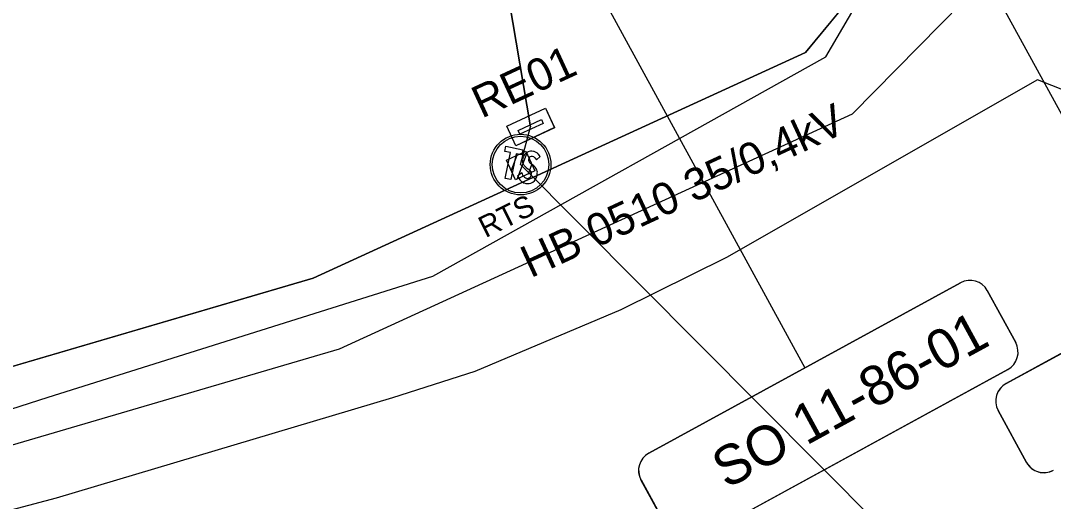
# Model space of a CAD drawing. Extents: x -9100 to -8660, y -10901 to -10569.
# Drawn here: x -8996.47 to -8948.33, y -10841.15 to -10818.76 of the extents above; entities that cross this region are included whole.
import ezdxf

# ---------------------------------------------------------------- set-up
doc = ezdxf.new("R2010")
doc.units = 0
for name, color, linetype in [('01_CETIN - sítě s NN elektropřípojky', 7, 'Continuous'), ('01_CETIN- zaměřené a kotované vnitřní STP', 7, 'Continuous'), ('04_ČEZ Distribuce - zařízení VN - nadzemní vedení', 7, 'Continuous'), ('bubliny', 7, 'Continuous'), ('HranDP', 7, 'Continuous'), ('Hranice parcel', 7, 'Continuous'), ('SDĚL__BUBLINY', 7, 'Continuous'), ('SO118601 - demontáž', 7, 'Continuous'), ('SO118601 - rozvaděče  popis', 7, 'Continuous'), ('SO118601 - trasa NN', 7, 'Continuous'), ('SO118601 - uzemnění', 7, 'Continuous'), ('Stanice', 7, 'Continuous'), ('Vrstva 25', 7, 'Continuous'), ('Vrstva 36', 7, 'Continuous'), ('Vrstva 49', 7, 'Continuous')]:
    doc.layers.add(name, color=color, linetype=linetype)

msp = doc.modelspace()

# ---------------------------------------------------------------- linework, layer by layer
at = {"layer": '01_CETIN - sítě s NN elektropřípojky'}
msp.add_lwpolyline([(-8917.077, -10839.873), (-8942.153, -10824.246), (-8949.063, -10821.506), (-8963.569, -10829.782), (-8968.494, -10832.229), (-8975.302, -10835.095), (-8979.139, -10836.327), (-8994.813, -10841.003), (-9019.054, -10847.417), (-9034.972, -10852.38), (-9045.31, -10855.336), (-9052.978, -10857.159)], dxfattribs=at)
at = {"layer": '01_CETIN- zaměřené a kotované vnitřní STP'}
msp.add_lwpolyline([(-8917.077, -10839.873), (-8942.153, -10824.246), (-8949.063, -10821.506), (-8963.569, -10829.782), (-8968.494, -10832.229), (-8975.302, -10835.095), (-8979.139, -10836.327), (-8994.813, -10841.003), (-9019.054, -10847.417), (-9034.972, -10852.38), (-9045.31, -10855.336), (-9052.978, -10857.159)], dxfattribs=at)
at = {"layer": '04_ČEZ Distribuce - zařízení VN - nadzemní vedení'}
msp.add_line((-8973.165, -10825.461), (-8944.116, -10854.646), dxfattribs=at)
at = {"layer": 'bubliny'}
for points in [[(-8936.004, -10827.724), (-8950.533, -10835.662)], [(-8952.656, -10830.964), (-8967.185, -10838.902)], [(-8950.085, -10833.752), (-8951.408, -10831.33)], [(-8964.98, -10842.938), (-8950.451, -10835)], [(-8950.899, -10836.91), (-8949.576, -10839.332)], [(-8967.551, -10840.15), (-8966.228, -10842.572)]]:
    msp.add_lwpolyline(points, dxfattribs=at)
for centre, start, end in [((-8952.215, -10831.771), 28.6505, 118.6505), ((-8950.892, -10834.193), 298.6505, 28.6505), ((-8950.092, -10836.469), 118.6505, 208.6505), ((-8966.744, -10839.709), 118.6505, 208.6505), ((-8948.769, -10838.891), 208.6505, 298.6505)]:
    msp.add_arc(centre, 0.92, start, end, dxfattribs=at)
at = {"layer": 'HranDP'}
for p, q in [((-8953.298, -10812.273), (-8959.89, -10820.238)), ((-8959.89, -10820.238), (-8982.832, -10830.758)), ((-8982.832, -10830.758), (-9000.486, -10835.925))]:
    msp.add_line(p, q, dxfattribs=at)
at = {"layer": 'Hranice parcel'}
for points in [[(-9055.928, -10851.76), (-9053.006, -10851.261), (-9031.397, -10845.928), (-9000.486, -10835.925), (-8982.832, -10830.758), (-8959.89, -10820.238), (-8953.298, -10812.273)], [(-9019.074, -10845.627), (-8999.459, -10839.271), (-8981.599, -10834.044), (-8957.699, -10823.088), (-8949.49, -10814.752)]]:
    msp.add_lwpolyline(points, dxfattribs=at)
at = {"layer": 'SDĚL__BUBLINY'}
for p, q in [((-8975.687, -10806.074), (-8959.921, -10834.933)), ((-8956.098, -10808.21), (-8943.268, -10831.693)), ((-8950.534, -10835.663), (-8936.004, -10827.724)), ((-8967.186, -10838.902), (-8952.656, -10830.964)), ((-8951.408, -10831.33), (-8950.085, -10833.752)), ((-8950.451, -10835), (-8964.981, -10842.938)), ((-8949.577, -10839.332), (-8950.9, -10836.911)), ((-8966.229, -10842.572), (-8967.552, -10840.151))]:
    msp.add_line(p, q, dxfattribs=at)
for centre, start, end in [((-8952.215, -10831.771), 28.65, 118.65), ((-8950.892, -10834.193), 298.65, 28.65), ((-8950.093, -10836.47), 118.65, 208.65), ((-8966.745, -10839.71), 118.65, 208.65), ((-8948.77, -10838.891), 208.65, 298.65)]:
    msp.add_arc(centre, 0.92, start, end, dxfattribs=at)
at = {"layer": 'SO118601 - demontáž'}
for points in [[(-8971.577, -10823.735), (-8973.39, -10824.579), (-8973.812, -10823.673), (-8971.999, -10822.828)], [(-8972.109, -10823.541), (-8973.196, -10824.048), (-8973.281, -10823.866), (-8972.193, -10823.36)]]:
    msp.add_lwpolyline(points, close=True, dxfattribs=at)
at = {"layer": 'SO118601 - trasa NN'}
msp.add_lwpolyline([(-8973.165, -10825.461), (-8972.695, -10823.704), (-8975.687, -10806.074), (-8973.81, -10805.142), (-8975.545, -10801.649)], dxfattribs=at)
at = {"layer": 'SO118601 - uzemnění'}
msp.add_lwpolyline([(-8975.687, -10806.074), (-8972.695, -10823.704)], dxfattribs=at)
at = {"layer": 'Stanice'}
msp.add_lwpolyline([(-8973.856, -10824.604), (-8973.062, -10824.768), (-8973.112, -10825.006), (-8973.375, -10824.952), (-8973.624, -10826.159), (-8973.884, -10826.105), (-8973.635, -10824.898), (-8973.905, -10824.843)], close=True, dxfattribs=at)
for points in [[(-8972.495, -10825.143), (-8972.43, -10825.241), (-8972.257, -10825.078), (-8972.301, -10825.016), (-8972.336, -10824.978)], [(-8972.546, -10825.519), (-8972.61, -10825.467), (-8972.681, -10825.42), (-8972.719, -10825.387), (-8972.752, -10825.355)], [(-8973.028, -10826), (-8973.061, -10825.947), (-8973.082, -10825.886), (-8973.102, -10825.851), (-8973.301, -10825.993), (-8973.246, -10826.098), (-8973.201, -10826.165), (-8973.137, -10826.228)], [(-8972.901, -10825.596), (-8972.828, -10825.655), (-8972.767, -10825.695), (-8972.72, -10825.734)]]:
    msp.add_lwpolyline(points, dxfattribs=at)
for radius in [1.412, 1.32]:
    msp.add_circle((-8973.165, -10825.461), radius, dxfattribs=at)
for centre, radius, start, end in [((-8972.645, -10825.255), 0.426, 135.9746, 162.995), ((-8972.683, -10825.209), 0.366, 113.7008, 136.9799), ((-8972.658, -10825.207), 0.376, 75.7036, 117.2623), ((-8972.63, -10825.183), 0.346, 55.5188, 79.2128), ((-8972.616, -10825.222), 0.372, 41.1648, 60.7383), ((-8972.805, -10825.276), 0.273, 170.5247, 186.399), ((-8972.803, -10825.303), 0.274, 180.694, 219.2977), ((-8972.692, -10825.263), 0.384, 159.6633, 175.0898), ((-8972.562, -10825.161), 0.552, 214.8444, 232.0967), ((-8972.624, -10825.249), 0.176, 124.8082, 181.6492), ((-8972.604, -10825.221), 0.199, 189.5219, 222.263), ((-8972.632, -10825.255), 0.178, 39.3918, 121.6274), ((-8972.904, -10825.956), 0.564, 31.0095, 50.716), ((-8972.861, -10825.894), 0.198, 212.2742, 247.1699), ((-8972.878, -10825.885), 0.228, 306.9588, 13.2719), ((-8972.923, -10825.932), 0.284, 20.437, 44.3027), ((-8972.81, -10825.878), 0.425, 335.1913, 2.9723), ((-8972.708, -10825.817), 0.326, 353.0016, 27.6829), ((-8972.895, -10826.002), 0.331, 223.1068, 252.3086), ((-8972.818, -10825.825), 0.523, 250.1369, 285.3736), ((-8972.847, -10825.924), 0.177, 239.115, 306.3968), ((-8972.823, -10825.939), 0.416, 290.1471, 343.5142)]:
    msp.add_arc(centre, radius, start, end, dxfattribs=at)
at = {"layer": 'Vrstva 25'}
msp.add_lwpolyline([(-8973.391, -10824.58), (-8973.811, -10823.672), (-8971.996, -10822.833), (-8971.576, -10823.74), (-8973.391, -10824.58)], dxfattribs=at)
at = {"layer": 'Vrstva 36'}
for p, q in [((-8973.598, -10825.753), (-8973.33, -10825.025)), ((-8973.304, -10826.115), (-8972.872, -10824.939)), ((-8972.791, -10825.878), (-8972.635, -10825.453))]:
    msp.add_line(p, q, dxfattribs=at)
msp.add_lwpolyline([(-8973.408, -10826.163), (-8973.828, -10825.255), (-8972.92, -10824.836), (-8972.5, -10825.743)], close=True, dxfattribs=at)
at = {"layer": 'Vrstva 49'}
msp.add_lwpolyline([(-9055.198, -10853.095), (-9026.593, -10846.378), (-8995.195, -10836.296), (-8977.248, -10830.66), (-8958.939, -10820.434), (-8954.451, -10812.764), (-8958.4, -10809.815), (-8983.47, -10803.815), (-8986.901, -10802.53)], dxfattribs=at)

# ---------------------------------------------------------------- texts
at = {"layer": 'SDĚL__BUBLINY'}
msp.add_text('SO 11-86-01', height=1.83967, rotation=28.65, dxfattribs=at).set_placement((-8963.563, -10840.591))
at = {"layer": 'SO118601 - rozvaděče  popis'}
msp.add_text('RTS', height=1, rotation=26.4087, dxfattribs=at).set_placement((-8974.801, -10828.894))
at = {"layer": 'Vrstva 25'}
msp.add_text('RE01', height=1.5, rotation=24.8233, dxfattribs=at).set_placement((-8974.981, -10823.326))
at = {"layer": 'Vrstva 36'}
msp.add_text('HB 0510 35/0,4kV', height=1.5, rotation=24.8233, dxfattribs=at).set_placement((-8972.694, -10830.761))

doc.saveas('drawing.dxf')
